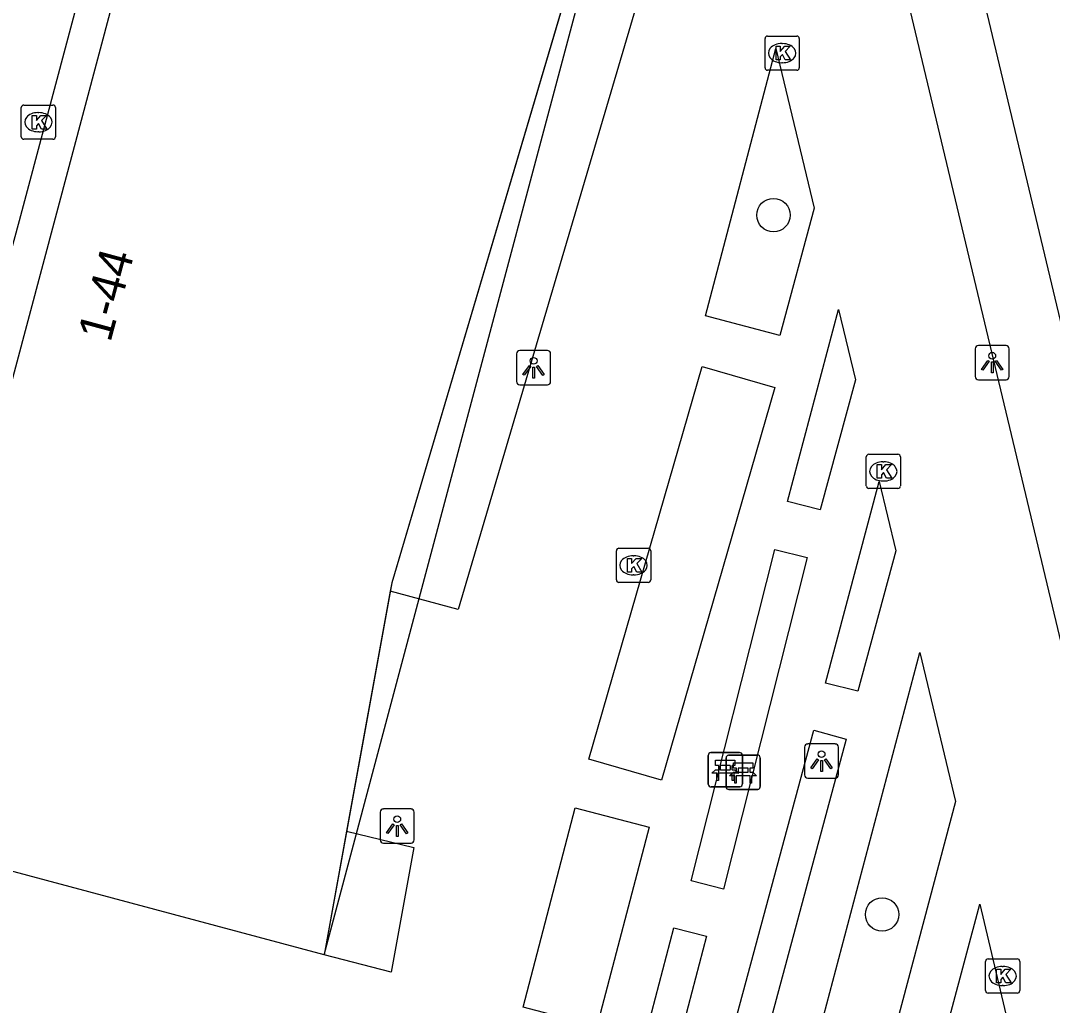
# Model space of a CAD drawing. Extents: x 160676 to 161153, y 383244 to 383713.
# Drawn here: x 160862.26 to 160892.41, y 383507.76 to 383536.53 of the extents above; entities that cross this region are included whole.
import ezdxf

# ---------------------------------------------------------------- set-up
doc = ezdxf.new("R2010")
doc.units = 0
for name, color, linetype in [('IMGEO_Bank', 7, 'Continuous'), ('IMGEO_Boom', 7, 'Continuous'), ('IMGEO_Kolk', 7, 'Continuous'), ('IMGEO_Lichtpunt', 7, 'Continuous'), ('IMGEO_Pand', 7, 'Continuous'), ('IMGEO_Pand_nummerreeks', 7, 'Continuous'), ('IMGEO_Pand_overbouw', 7, 'Continuous'), ('IMGEO_Voetpad_open', 7, 'Continuous')]:
    doc.layers.add(name, color=color, linetype=linetype)

msp = doc.modelspace()

# ---------------------------------------------------------------- linework, layer by layer
at = {"layer": 'IMGEO_Bank'}
for p, q in [((160882.357, 383514.22), (160882.357, 383515.061)), ((160882.357, 383515.061), (160882.357, 383514.22)), ((160882.432, 383515.145), (160883.273, 383515.145)), ((160883.273, 383515.145), (160882.432, 383515.145)), ((160882.878, 383514.146), (160882.878, 383514.987)), ((160882.878, 383514.987), (160882.878, 383514.146)), ((160882.953, 383515.071), (160883.794, 383515.071)), ((160883.794, 383515.071), (160882.953, 383515.071)), ((160883.357, 383515.07), (160883.357, 383514.229)), ((160883.357, 383514.229), (160883.357, 383515.07)), ((160883.878, 383514.996), (160883.878, 383514.155)), ((160883.878, 383514.155), (160883.878, 383514.996)), ((160882.666, 383514.651), (160882.666, 383514.757)), ((160882.71, 383514.757), (160882.71, 383514.651)), ((160882.998, 383514.763), (160882.716, 383514.763)), ((160882.716, 383514.645), (160882.998, 383514.645)), ((160883.004, 383514.651), (160883.004, 383514.757)), ((160883.048, 383514.757), (160883.048, 383514.651)), ((160883.187, 383514.577), (160883.187, 383514.683)), ((160883.231, 383514.683), (160883.231, 383514.577)), ((160883.519, 383514.689), (160883.237, 383514.689)), ((160883.237, 383514.571), (160883.519, 383514.571)), ((160883.525, 383514.577), (160883.525, 383514.683)), ((160883.569, 383514.683), (160883.569, 383514.577)), ((160883.054, 383514.543), (160882.661, 383514.543)), ((160883.575, 383514.469), (160883.182, 383514.469)), ((160883.282, 383514.145), (160882.441, 383514.145)), ((160882.441, 383514.145), (160883.282, 383514.145)), ((160883.803, 383514.071), (160882.962, 383514.071)), ((160882.962, 383514.071), (160883.803, 383514.071))]:
    msp.add_line(p, q, dxfattribs=at)
for points in [[(160882.66, 383514.763), (160882.574, 383514.763), (160882.574, 383514.924), (160883.137, 383514.924), (160883.137, 383514.763), (160883.054, 383514.763)], [(160882.604, 383514.543), (160882.462, 383514.543), (160882.574, 383514.645), (160882.66, 383514.645)], [(160883.125, 383514.469), (160882.983, 383514.469), (160883.095, 383514.571), (160883.181, 383514.571)], [(160883.054, 383514.645), (160883.137, 383514.645), (160883.249, 383514.543), (160883.11, 383514.543)], [(160883.181, 383514.689), (160883.095, 383514.689), (160883.095, 383514.85), (160883.658, 383514.85), (160883.658, 383514.689), (160883.575, 383514.689)], [(160883.575, 383514.571), (160883.658, 383514.571), (160883.77, 383514.469), (160883.631, 383514.469)], [(160882.654, 383514.536), (160882.654, 383514.329), (160882.611, 383514.329), (160882.611, 383514.536)], [(160883.104, 383514.536), (160883.104, 383514.329), (160883.06, 383514.329), (160883.06, 383514.536)], [(160883.175, 383514.462), (160883.175, 383514.255), (160883.132, 383514.255), (160883.132, 383514.462)], [(160883.625, 383514.462), (160883.625, 383514.255), (160883.581, 383514.255), (160883.581, 383514.462)]]:
    msp.add_lwpolyline(points, dxfattribs=at)
for centre, radius, start, end in [((160882.435, 383515.067), 0.0779, 92.4484, 184.2845), ((160882.435, 383515.067), 0.0779, 92.4484, 184.2845), ((160882.956, 383514.993), 0.0779, 92.4484, 184.2845), ((160882.956, 383514.993), 0.0779, 92.4484, 184.2845), ((160883.279, 383515.067), 0.0779, 2.4484, 94.2845), ((160883.279, 383515.067), 0.0779, 2.4484, 94.2845), ((160883.8, 383514.993), 0.0779, 2.4484, 94.2845), ((160883.8, 383514.993), 0.0779, 2.4484, 94.2845), ((160882.659, 383514.756), 0.00671, 2.8957, 87.1043), ((160882.659, 383514.652), 0.00671, 272.8957, 357.1043), ((160882.716, 383514.756), 0.00671, 92.8957, 177.1043), ((160882.716, 383514.652), 0.00671, 182.8957, 267.1043), ((160882.998, 383514.756), 0.00671, 2.8957, 87.1043), ((160882.998, 383514.652), 0.00671, 272.8957, 357.1043), ((160883.055, 383514.756), 0.00671, 92.8957, 177.1043), ((160883.055, 383514.652), 0.00671, 182.8957, 267.1043), ((160883.18, 383514.682), 0.00671, 2.8957, 87.1043), ((160883.18, 383514.578), 0.00671, 272.8957, 357.1043), ((160883.237, 383514.682), 0.00671, 92.8957, 177.1043), ((160883.237, 383514.578), 0.00671, 182.8957, 267.1043), ((160883.519, 383514.682), 0.00671, 2.8957, 87.1043), ((160883.519, 383514.578), 0.00671, 272.8957, 357.1043), ((160883.576, 383514.682), 0.00671, 92.8957, 177.1043), ((160883.576, 383514.578), 0.00671, 182.8957, 267.1043), ((160882.604, 383514.536), 0.00671, 2.8957, 87.1043), ((160882.661, 383514.536), 0.00671, 92.8957, 177.1043), ((160883.053, 383514.536), 0.00671, 2.8957, 87.1043), ((160883.11, 383514.536), 0.00671, 92.8957, 177.1043), ((160883.125, 383514.462), 0.00671, 2.8957, 87.1043), ((160883.182, 383514.462), 0.00671, 92.8957, 177.1043), ((160883.574, 383514.462), 0.00671, 2.8957, 87.1043), ((160883.631, 383514.462), 0.00671, 92.8957, 177.1043), ((160882.435, 383514.223), 0.0779, 182.4484, 274.2845), ((160882.435, 383514.223), 0.0779, 182.4484, 274.2845), ((160882.956, 383514.149), 0.0779, 182.4484, 274.2845), ((160882.956, 383514.149), 0.0779, 182.4484, 274.2845), ((160883.279, 383514.223), 0.0779, 272.4484, 4.2845), ((160883.279, 383514.223), 0.0779, 272.4484, 4.2845), ((160883.8, 383514.149), 0.0779, 272.4484, 4.2845), ((160883.8, 383514.149), 0.0779, 272.4484, 4.2845)]:
    msp.add_arc(centre, radius, start, end, dxfattribs=at)
at = {"layer": 'IMGEO_Boom'}
for centre in [(160884.265, 383530.85), (160887.439, 383510.414)]:
    msp.add_circle(centre, 0.489, dxfattribs=at)
at = {"layer": 'IMGEO_Kolk'}
for p, q in [((160884.018, 383535.157), (160884.018, 383536.009)), ((160884.093, 383536.083), (160884.945, 383536.083)), ((160885.019, 383536.009), (160885.019, 383535.157)), ((160884.506, 383535.863), (160884.531, 383535.863)), ((160884.945, 383535.083), (160884.093, 383535.083)), ((160884.529, 383535.303), (160884.504, 383535.303)), ((160862.282, 383533.14), (160862.282, 383533.992)), ((160862.357, 383534.066), (160863.209, 383534.066)), ((160863.283, 383533.992), (160863.283, 383533.14)), ((160862.77, 383533.846), (160862.795, 383533.846)), ((160862.793, 383533.286), (160862.768, 383533.286)), ((160863.209, 383533.066), (160862.357, 383533.066)), ((160886.975, 383522.935), (160886.975, 383523.787)), ((160887.05, 383523.861), (160887.902, 383523.861)), ((160887.463, 383523.641), (160887.488, 383523.641)), ((160887.976, 383523.787), (160887.976, 383522.935)), ((160887.486, 383523.081), (160887.461, 383523.081)), ((160887.902, 383522.861), (160887.05, 383522.861)), ((160879.675, 383520.191), (160879.675, 383521.043)), ((160879.75, 383521.117), (160880.602, 383521.117)), ((160880.163, 383520.897), (160880.188, 383520.897)), ((160880.676, 383521.043), (160880.676, 383520.191)), ((160880.186, 383520.337), (160880.161, 383520.337)), ((160880.602, 383520.117), (160879.75, 383520.117)), ((160890.461, 383508.19), (160890.461, 383509.042)), ((160890.536, 383509.116), (160891.388, 383509.116)), ((160890.949, 383508.896), (160890.974, 383508.896)), ((160891.462, 383509.042), (160891.462, 383508.19)), ((160890.972, 383508.336), (160890.947, 383508.336)), ((160891.388, 383508.116), (160890.536, 383508.116))]:
    msp.add_line(p, q, dxfattribs=at)
for points in [[(160884.018, 383535.157), (160884.018, 383536.009)], [(160884.093, 383536.083), (160884.945, 383536.083)], [(160885.019, 383536.009), (160885.019, 383535.157)], [(160884.339, 383535.783), (160884.462, 383535.783), (160884.462, 383535.632), (160884.592, 383535.783), (160884.756, 383535.783), (160884.61, 383535.632), (160884.763, 383535.383), (160884.611, 383535.383), (160884.526, 383535.547), (160884.462, 383535.48), (160884.462, 383535.383), (160884.339, 383535.383), (160884.339, 383535.783)], [(160884.945, 383535.083), (160884.093, 383535.083)], [(160862.282, 383533.14), (160862.282, 383533.992)], [(160862.357, 383534.066), (160863.209, 383534.066)], [(160863.283, 383533.992), (160863.283, 383533.14)], [(160862.603, 383533.766), (160862.726, 383533.766), (160862.726, 383533.615), (160862.856, 383533.766), (160863.02, 383533.766), (160862.874, 383533.615), (160863.027, 383533.366), (160862.875, 383533.366), (160862.79, 383533.53), (160862.726, 383533.463), (160862.726, 383533.366), (160862.603, 383533.366), (160862.603, 383533.766)], [(160863.209, 383533.066), (160862.357, 383533.066)], [(160886.975, 383522.935), (160886.975, 383523.787)], [(160887.05, 383523.861), (160887.902, 383523.861)], [(160887.976, 383523.787), (160887.976, 383522.935)], [(160887.296, 383523.561), (160887.419, 383523.561), (160887.419, 383523.41), (160887.549, 383523.561), (160887.713, 383523.561), (160887.567, 383523.41), (160887.72, 383523.161), (160887.568, 383523.161), (160887.483, 383523.325), (160887.419, 383523.258), (160887.419, 383523.161), (160887.296, 383523.161), (160887.296, 383523.561)], [(160887.902, 383522.861), (160887.05, 383522.861)], [(160879.675, 383520.191), (160879.675, 383521.043)], [(160879.75, 383521.117), (160880.602, 383521.117)], [(160880.676, 383521.043), (160880.676, 383520.191)], [(160879.996, 383520.817), (160880.119, 383520.817), (160880.119, 383520.666), (160880.249, 383520.817), (160880.413, 383520.817), (160880.267, 383520.666), (160880.42, 383520.417), (160880.268, 383520.417), (160880.183, 383520.581), (160880.119, 383520.514), (160880.119, 383520.417), (160879.996, 383520.417), (160879.996, 383520.817)], [(160880.602, 383520.117), (160879.75, 383520.117)], [(160890.461, 383508.19), (160890.461, 383509.042)], [(160890.536, 383509.116), (160891.388, 383509.116)], [(160891.462, 383509.042), (160891.462, 383508.19)], [(160890.782, 383508.816), (160890.905, 383508.816), (160890.905, 383508.665), (160891.035, 383508.816), (160891.199, 383508.816), (160891.053, 383508.665), (160891.206, 383508.416), (160891.054, 383508.416), (160890.969, 383508.58), (160890.905, 383508.513), (160890.905, 383508.416), (160890.782, 383508.416), (160890.782, 383508.816)], [(160891.388, 383508.116), (160890.536, 383508.116)]]:
    msp.add_lwpolyline(points, dxfattribs=at)
for centre, start, end in [((160884.095, 383536.007), 91.552, 178.448), ((160884.095, 383536.007), 91.552, 178.448), ((160884.943, 383536.007), 1.552, 88.448), ((160884.943, 383536.007), 1.552, 88.448), ((160884.095, 383535.159), 181.552, 268.448), ((160884.095, 383535.159), 181.552, 268.448), ((160884.943, 383535.159), 271.552, 358.448), ((160884.943, 383535.159), 271.552, 358.448), ((160862.359, 383533.99), 91.552, 178.448), ((160862.359, 383533.99), 91.552, 178.448), ((160863.207, 383533.99), 1.552, 88.448), ((160863.207, 383533.99), 1.552, 88.448), ((160862.359, 383533.142), 181.552, 268.448), ((160862.359, 383533.142), 181.552, 268.448), ((160863.207, 383533.142), 271.552, 358.448), ((160863.207, 383533.142), 271.552, 358.448), ((160887.052, 383523.785), 91.552, 178.448), ((160887.052, 383523.785), 91.552, 178.448), ((160887.9, 383523.785), 1.552, 88.448), ((160887.9, 383523.785), 1.552, 88.448), ((160887.052, 383522.937), 181.552, 268.448), ((160887.052, 383522.937), 181.552, 268.448), ((160887.9, 383522.937), 271.552, 358.448), ((160887.9, 383522.937), 271.552, 358.448), ((160879.752, 383521.041), 91.552, 178.448), ((160879.752, 383521.041), 91.552, 178.448), ((160880.6, 383521.041), 1.552, 88.448), ((160880.6, 383521.041), 1.552, 88.448), ((160879.752, 383520.193), 181.552, 268.448), ((160879.752, 383520.193), 181.552, 268.448), ((160880.6, 383520.193), 271.552, 358.448), ((160880.6, 383520.193), 271.552, 358.448), ((160890.538, 383509.04), 91.552, 178.448), ((160890.538, 383509.04), 91.552, 178.448), ((160891.386, 383509.04), 1.552, 88.448), ((160891.386, 383509.04), 1.552, 88.448), ((160890.538, 383508.192), 181.552, 268.448), ((160890.538, 383508.192), 181.552, 268.448), ((160891.386, 383508.192), 271.552, 358.448), ((160891.386, 383508.192), 271.552, 358.448)]:
    msp.add_arc(centre, 0.0765, start, end, dxfattribs=at)
for centre, major_axis, ratio, start_param, end_param in [((160884.505, 383535.583), (-0.387, 0.002), 0.722429, 4.712389, 7.853982), ((160884.53, 383535.583), (-0.39, 0.002), 0.717154, 1.570796, 4.712389), ((160862.769, 383533.566), (-0.387, 0.002), 0.722429, 4.712389, 7.853982), ((160862.794, 383533.566), (-0.39, 0.002), 0.717154, 1.570796, 4.712389), ((160887.462, 383523.361), (-0.387, 0.002), 0.722429, 4.712389, 7.853982), ((160887.487, 383523.361), (-0.39, 0.002), 0.717154, 1.570796, 4.712389), ((160880.162, 383520.617), (-0.387, 0.002), 0.722429, 4.712389, 7.853982), ((160880.187, 383520.617), (-0.39, 0.002), 0.717154, 1.570796, 4.712389), ((160890.948, 383508.616), (-0.387, 0.002), 0.722429, 4.712389, 7.853982), ((160890.973, 383508.616), (-0.39, 0.002), 0.717154, 1.570796, 4.712389)]:
    msp.add_ellipse(centre, major_axis=major_axis, ratio=ratio, start_param=start_param, end_param=end_param, dxfattribs=at)
at = {"layer": 'IMGEO_Lichtpunt'}
for p, q in [((160890.158, 383526.943), (160890.158, 383526.136)), ((160890.158, 383526.943), (160890.158, 383526.136)), ((160891.06, 383527.038), (160890.252, 383527.038)), ((160891.06, 383527.038), (160890.252, 383527.038)), ((160891.154, 383526.136), (160891.154, 383526.943)), ((160891.154, 383526.136), (160891.154, 383526.943)), ((160876.756, 383526.795), (160876.756, 383525.988)), ((160876.756, 383526.795), (160876.756, 383525.988)), ((160877.658, 383526.89), (160876.85, 383526.89)), ((160877.658, 383526.89), (160876.85, 383526.89)), ((160877.752, 383525.988), (160877.752, 383526.795)), ((160877.752, 383525.988), (160877.752, 383526.795)), ((160890.252, 383526.042), (160891.06, 383526.042)), ((160890.252, 383526.042), (160891.06, 383526.042)), ((160876.85, 383525.894), (160877.658, 383525.894)), ((160876.85, 383525.894), (160877.658, 383525.894)), ((160885.17, 383515.301), (160885.17, 383514.494)), ((160885.17, 383515.301), (160885.17, 383514.494)), ((160886.072, 383515.396), (160885.264, 383515.396)), ((160886.072, 383515.396), (160885.264, 383515.396)), ((160886.166, 383514.494), (160886.166, 383515.301)), ((160886.166, 383514.494), (160886.166, 383515.301)), ((160885.264, 383514.4), (160886.072, 383514.4)), ((160885.264, 383514.4), (160886.072, 383514.4)), ((160872.77, 383513.402), (160872.77, 383512.595)), ((160872.77, 383513.402), (160872.77, 383512.595)), ((160873.672, 383513.497), (160872.864, 383513.497)), ((160873.672, 383513.497), (160872.864, 383513.497)), ((160873.766, 383512.595), (160873.766, 383513.402)), ((160873.766, 383512.595), (160873.766, 383513.402)), ((160872.864, 383512.501), (160873.672, 383512.501)), ((160872.864, 383512.501), (160873.672, 383512.501))]:
    msp.add_line(p, q, dxfattribs=at)
for points in [[(160877.13, 383526.459), (160877.169, 383526.431), (160876.981, 383526.169), (160876.943, 383526.196), (160877.13, 383526.459)], [(160877.232, 383526.411), (160877.279, 383526.411), (160877.279, 383526.089), (160877.232, 383526.089), (160877.232, 383526.411)], [(160877.342, 383526.431), (160877.38, 383526.458), (160877.567, 383526.196), (160877.528, 383526.168), (160877.342, 383526.431)], [(160890.532, 383526.607), (160890.571, 383526.579), (160890.383, 383526.317), (160890.345, 383526.344), (160890.532, 383526.607)], [(160890.634, 383526.559), (160890.681, 383526.559), (160890.681, 383526.237), (160890.634, 383526.237), (160890.634, 383526.559)], [(160890.744, 383526.579), (160890.782, 383526.606), (160890.969, 383526.344), (160890.93, 383526.316), (160890.744, 383526.579)], [(160885.544, 383514.965), (160885.583, 383514.937), (160885.395, 383514.675), (160885.357, 383514.702), (160885.544, 383514.965)], [(160885.646, 383514.917), (160885.693, 383514.917), (160885.693, 383514.595), (160885.646, 383514.595), (160885.646, 383514.917)], [(160885.756, 383514.937), (160885.794, 383514.964), (160885.981, 383514.702), (160885.942, 383514.674), (160885.756, 383514.937)], [(160873.144, 383513.066), (160873.183, 383513.038), (160872.995, 383512.776), (160872.957, 383512.803), (160873.144, 383513.066)], [(160873.356, 383513.038), (160873.394, 383513.065), (160873.581, 383512.803), (160873.542, 383512.775), (160873.356, 383513.038)], [(160873.246, 383513.018), (160873.293, 383513.018), (160873.293, 383512.696), (160873.246, 383512.696), (160873.246, 383513.018)]]:
    msp.add_lwpolyline(points, dxfattribs=at)
for centre in [(160877.255, 383526.593), (160890.657, 383526.741), (160885.669, 383515.099), (160873.269, 383513.2)]:
    msp.add_circle(centre, 0.0994, dxfattribs=at)
for centre, start, end in [((160890.252, 383526.943), 90, 180), ((160890.252, 383526.943), 90, 180), ((160891.06, 383526.943), 0, 90), ((160891.06, 383526.943), 0, 90), ((160876.85, 383526.795), 90, 180), ((160876.85, 383526.795), 90, 180), ((160877.658, 383526.795), 0, 90), ((160877.658, 383526.795), 0, 90), ((160890.252, 383526.136), 180, 270), ((160890.252, 383526.136), 180, 270), ((160891.06, 383526.136), 270, 0), ((160891.06, 383526.136), 270, 360), ((160876.85, 383525.988), 180, 270), ((160876.85, 383525.988), 180, 270), ((160877.658, 383525.988), 270, 0), ((160877.658, 383525.988), 270, 360), ((160885.264, 383515.301), 90, 180), ((160885.264, 383515.301), 90, 180), ((160886.072, 383515.301), 0, 90), ((160886.072, 383515.301), 0, 90), ((160885.264, 383514.494), 180, 270), ((160885.264, 383514.494), 180, 270), ((160886.072, 383514.494), 270, 0), ((160886.072, 383514.494), 270, 360), ((160872.864, 383513.402), 90, 180), ((160872.864, 383513.402), 90, 180), ((160873.672, 383513.402), 0, 90), ((160873.672, 383513.402), 0, 90), ((160872.864, 383512.595), 180, 270), ((160872.864, 383512.595), 180, 270), ((160873.672, 383512.595), 270, 0), ((160873.672, 383512.595), 270, 360)]:
    msp.add_arc(centre, 0.0946, start, end, dxfattribs=at)
at = {"layer": 'IMGEO_Pand'}
for points in [[(160858.445, 383512.624), (160866.56, 383543.07), (160867.863, 383547.958), (160869.136, 383548.269), (160882.404, 383551.516)], [(160897.386, 383507.933), (160889.292, 383541.869), (160888.301, 383546.023)], [(160879.332, 383541.136), (160873.107, 383520.103), (160873.064, 383519.865)], [(160873.064, 383519.865), (160871.79, 383512.852)], [(160871.79, 383512.852), (160871.132, 383509.231)], [(160871.132, 383509.231), (160860.534, 383512.065)]]:
    msp.add_lwpolyline(points, dxfattribs=at)
at = {"layer": 'IMGEO_Pand_overbouw'}
msp.add_lwpolyline([(160882.404, 383551.516), (160873.107, 383520.103), (160871.132, 383509.231)], close=True, dxfattribs=at)
at = {"layer": 'IMGEO_Voetpad_open'}
for points in [[(160857.402, 383512.924), (160862.229, 383530.692), (160867.046, 383548.766)], [(160897.386, 383507.933), (160895.279, 383507.435), (160890.493, 383527.494), (160886.195, 383545.514)], [(160879.332, 383541.136), (160881.31, 383540.557), (160875.055, 383519.322), (160873.064, 383519.865)], [(160884.337, 383535.716), (160885.452, 383531.052), (160884.45, 383527.328), (160882.275, 383527.908), (160884.337, 383535.716)], [(160886.165, 383528.095), (160886.664, 383526.034), (160885.625, 383522.243), (160884.676, 383522.483), (160886.165, 383528.095)], [(160882.182, 383526.424), (160884.301, 383525.812), (160880.989, 383514.338), (160878.87, 383514.95), (160882.182, 383526.424)], [(160887.355, 383523.068), (160887.837, 383521.04), (160886.734, 383516.939), (160885.788, 383517.177), (160887.355, 383523.068)], [(160884.3, 383521.082), (160885.247, 383520.843), (160882.802, 383511.156), (160881.855, 383511.395), (160884.3, 383521.082)], [(160888.545, 383518.071), (160889.58, 383513.712), (160887.26, 383504.948), (160885.21, 383505.485), (160888.545, 383518.071)], [(160882.838, 383506.122), (160885.44, 383515.796), (160886.389, 383515.541), (160883.787, 383505.867), (160882.838, 383506.122)], [(160876.945, 383507.705), (160878.471, 383513.535), (160880.632, 383512.969), (160879.106, 383507.14), (160876.945, 383507.705)], [(160871.79, 383512.852), (160873.758, 383512.376), (160873.089, 383508.73), (160871.132, 383509.231)], [(160890.293, 383510.718), (160891.949, 383503.711), (160888.663, 383504.586), (160890.293, 383510.718)], [(160881.356, 383510.028), (160882.309, 383509.777), (160881.449, 383506.505), (160880.496, 383506.755), (160881.356, 383510.028)]]:
    msp.add_lwpolyline(points, dxfattribs=at)

# ---------------------------------------------------------------- texts
at = {"layer": 'IMGEO_Pand_nummerreeks'}
msp.add_text('1-44', height=1, rotation=74.8799, dxfattribs=at).set_placement((160864.885, 383527.106))

doc.saveas('drawing.dxf')
